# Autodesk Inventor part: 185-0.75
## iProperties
Created: 2007-06
Part Number: 185-0.75
Document SubType Name: Modeling
Designer: btaylor
Density: 1 g/cm^3
Author: btaylor
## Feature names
1. Extrusion1
2. Extrusion2
3. Extrusion3
4. Chamfer1
5. Fillet1
6. Fillet2
7. Fillet3
